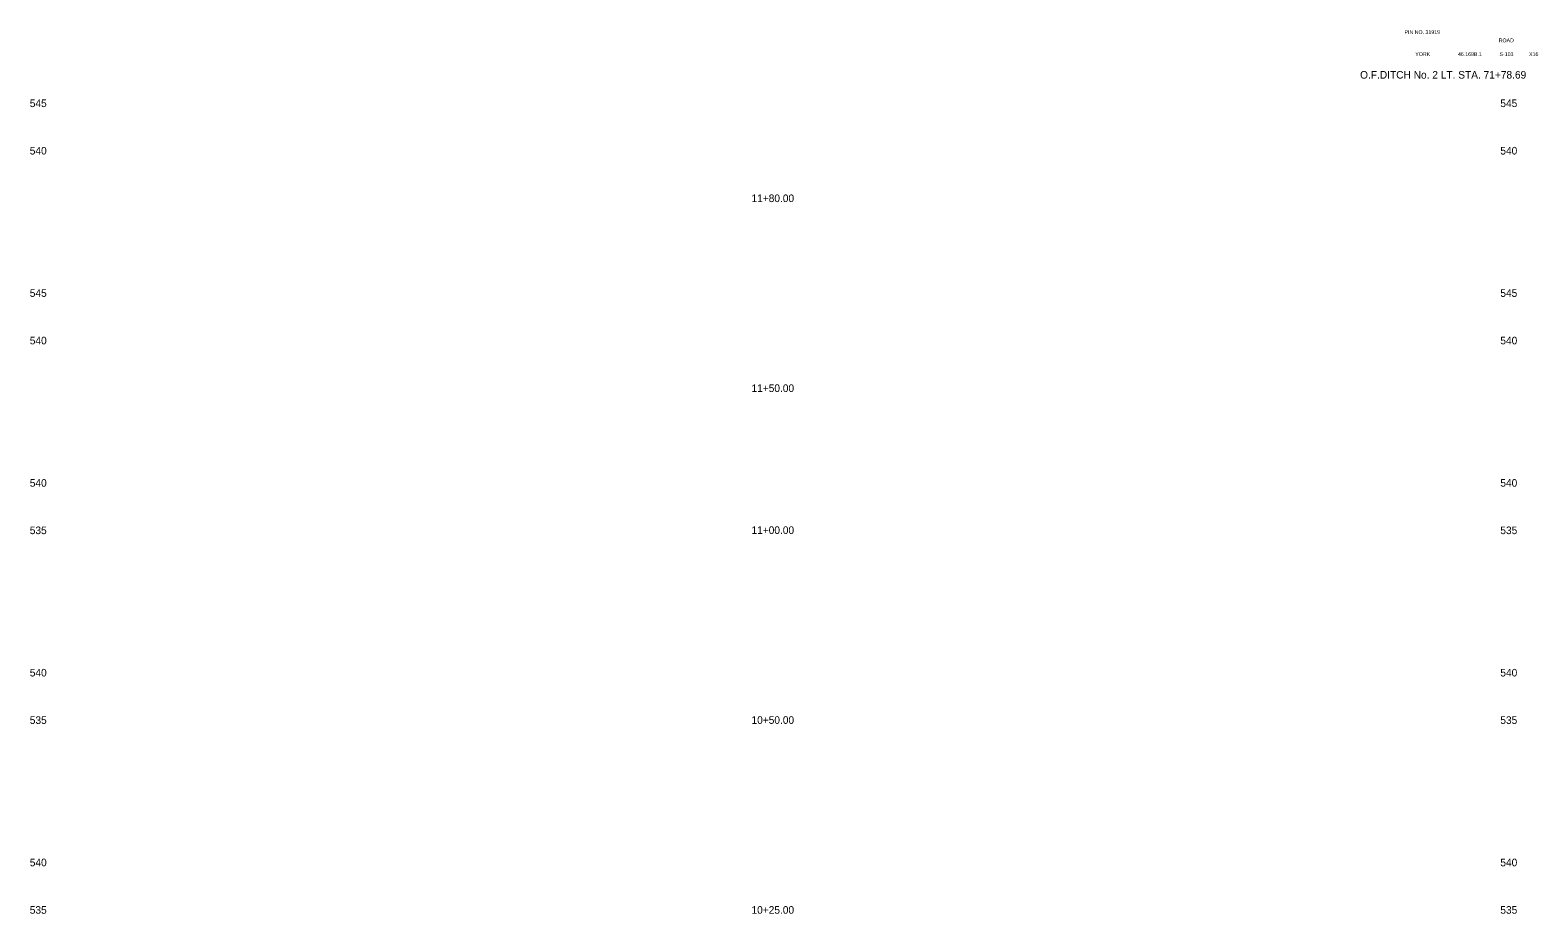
# Model space of a CAD drawing. Extents: x 1002 to 1161, y 1010 to 1103.
import ezdxf

# ---------------------------------------------------------------- set-up
doc = ezdxf.new("R2010")
doc.units = 0
for name, color, linetype in [('Level 25', 7, 'Continuous'), ('Level 41', 7, 'Continuous'), ('Level 56', 7, 'Continuous')]:
    doc.layers.add(name, color=color, linetype=linetype)

msp = doc.modelspace()

# ---------------------------------------------------------------- texts
at = {"layer": 'Level 25'}
for s, p in [('11+80.00', (1077.7, 1085.09)), ('11+50.00', (1077.7, 1065.08)), ('11+00.00', (1077.7, 1050.12)), ('10+50.00', (1077.7, 1030.11)), ('10+25.00', (1077.7, 1010.1))]:
    msp.add_text(s, height=0.8, dxfattribs=at).set_placement(p)
at = {"layer": 'Level 41'}
for s, height, p in [('PIN NO. 31919', 0.4, (1146.53, 1102.8)), ('ROAD', 0.4, (1156.46, 1101.93)), ('YORK', 0.4, (1147.67, 1100.48)), ('46.169B.1', 0.4, (1152.16, 1100.48)), ('S-103', 0.4, (1156.54, 1100.48)), ('X16', 0.4, (1159.66, 1100.48)), ('O.F.DITCH No. 2 LT. STA. 71+78.69', 0.8, (1141.85, 1098.1))]:
    msp.add_text(s, height=height, dxfattribs=at).set_placement(p)
at = {"layer": 'Level 56'}
for s, p in [('545', (1001.63, 1095.1)), ('545', (1156.63, 1095.1)), ('540', (1001.63, 1090.1)), ('540', (1156.63, 1090.1)), ('545', (1001.63, 1075.1)), ('545', (1156.63, 1075.1)), ('540', (1001.63, 1070.1)), ('540', (1156.63, 1070.1)), ('540', (1001.63, 1055.1)), ('540', (1156.63, 1055.1)), ('535', (1001.63, 1050.1)), ('535', (1156.63, 1050.1)), ('540', (1001.63, 1035.1)), ('540', (1156.63, 1035.1)), ('535', (1001.63, 1030.1)), ('535', (1156.63, 1030.1)), ('540', (1001.63, 1015.1)), ('540', (1156.63, 1015.1)), ('535', (1001.63, 1010.1)), ('535', (1156.63, 1010.1))]:
    msp.add_text(s, height=0.8, dxfattribs=at).set_placement(p)

doc.saveas('drawing.dxf')
